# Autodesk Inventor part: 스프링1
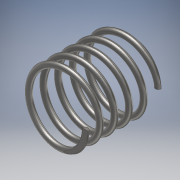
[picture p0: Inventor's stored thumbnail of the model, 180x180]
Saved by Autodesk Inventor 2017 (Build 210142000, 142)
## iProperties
Part Number: 스프링1
Material: 강철, 아연도금
Document SubType Name: Modeling
Designer: MRC
Density: 7.85 g/cm^3
Appearance: 아연도금
Mass: 1.07299 g
Surface Area: 21.725 cm^2
Volume: 1.07299 cm^3
Author: MRC
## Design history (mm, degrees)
sketch "스케치1"
  geometry: L1 (0, 0)-(0, 25.358); L2 (0, 25.358)-(11, 25.358); L3 (0, 0)-(11, 0); C1 r 1 at (11, 0)
  constraints: 6 end point, 2 horizontal, 1 centre point, 1 coincident, 1 vertical
  dimensions: "d0" = 25.35829 distance of L1.start L1.end (derived); "d2" = 22 diameter of L3.end L1; "d3" = 2 diameter of C1; "d4" = 22 diameter of L2.end L1
feature "코일1" pitch "d5" = 10; turns "d7" = 5; dims "d6" = 25.35829 (= d0), "d8" = 0, angle "d9" = 90 deg, angle "d10" = 90 deg, "d11" = 0, "d12" = 0
sketch "스케치2"
  geometry: L1 (-13.313, 0)-(15.035, 0); L2 (15.035, 0)-(15.035, 25.358); L3 (15.035, 25.358)-(-13.313, 25.358); L4 (-13.313, 25.358)-(-13.313, 0); 1 further point
  constraints: 8 end point, 2 parallel, 1 horizontal, 1 perpendicular
  dimensions: "d13" = 25.35829 distance of L1.end L2.end (= d0)
extrude "돌출1" sketch "스케치2" stored distance "d14" = 0; taper "d15" = 0 deg
node "솔리드1"
